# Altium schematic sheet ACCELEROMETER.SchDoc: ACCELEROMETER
size A4; CompanyName: Arduino srl; DrawnBy: Silvio Navaretti; DocumentNumber: ASX00039; SheetNumber: 6; SheetTotal: 8; RevAuthor: Silvio Navaretti
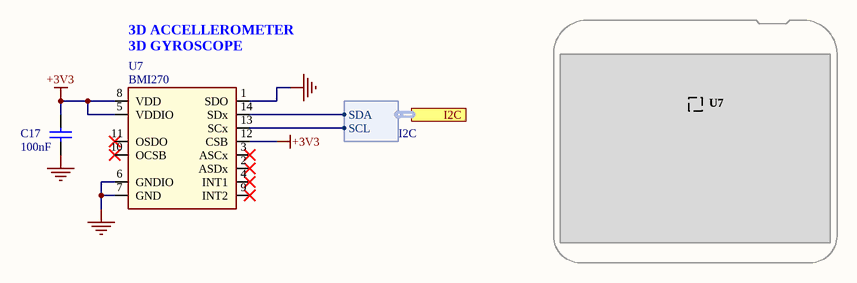
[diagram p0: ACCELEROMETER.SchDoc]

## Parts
C17  value 100nF  [CAP-0603]  (hidden comment: C0603C104K5RAC3190)
U7  BMI270  [VFLGA14]

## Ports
I2C (harness I2C)

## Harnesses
I2C: SDA, SCL

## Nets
+3V3: C17.2 U7.5(VDDIO) U7.8(VDD) U7.12(CSB)
GND: C17.1 U7.1(SDO) U7.6(GNDIO) U7.7(GND)
NetU7_13: U7.13(SCx) ; port I2C.SCL
NetU7_14: U7.14(SDx) ; port I2C.SDA

Not connected (* = marked no-connect by the designer): U7 2(ASDx)* 3(ASCx)* 4(INT1)* 9(INT2)* 10(OCSB)* 11(OSDO)*

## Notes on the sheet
- (near U7) 3D ACCELLEROMETER
  3D GYROSCOPE
- U7

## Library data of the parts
C17 = C0043-A.11: CAP CHIP 0603 100nF 50V X7R 10%; Manufacturer: KEMET; Code Arduino: 0015
U7 = U0217-A.3: IC IMU 6 AXIS 14VFLGA pin to pin alternative to LSM6DSOXTR; Manufacturer: Bosch Sensortech; Code Arduino: U0217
